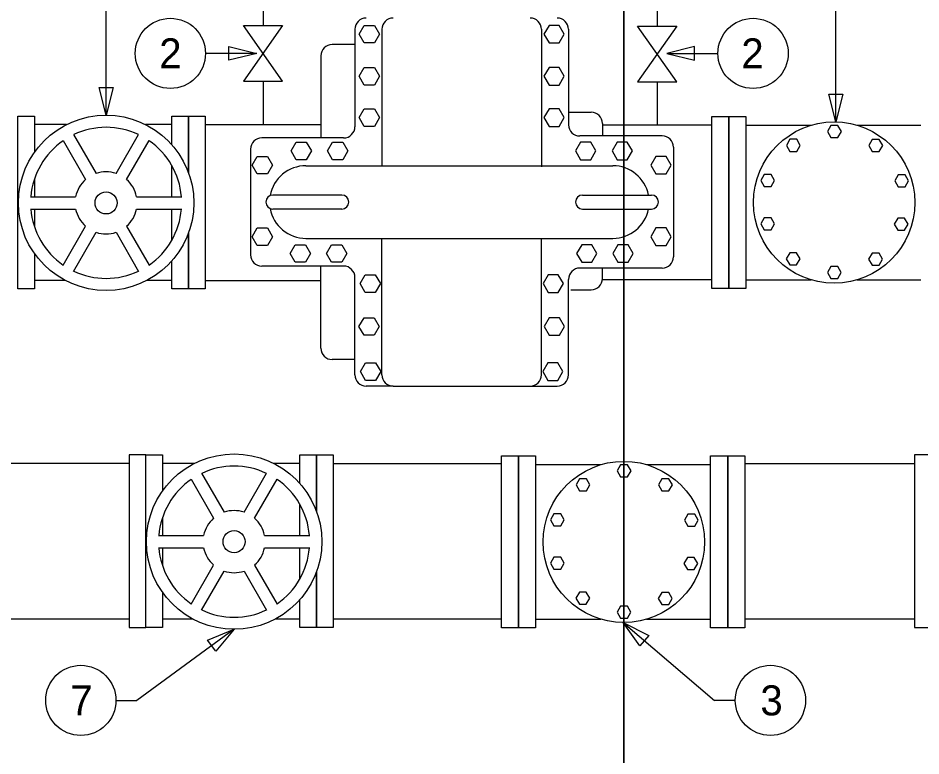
# Model space of a CAD drawing. Extents: x 10442.9 to 10533.9, y 10030 to 10079.1.
# Drawn here: x 10473.91 to 10495.58, y 10048.04 to 10065.76 of the extents above; entities that cross this region are included whole.
import ezdxf

# ---------------------------------------------------------------- set-up
doc = ezdxf.new("R2010")
doc.units = 0
for name, color, linetype in [('G-ANNO-NPLT', 7, 'Continuous'), ('G-ANNO-SYMB', 7, 'Continuous'), ('G-DETL-LINE', 7, 'Continuous')]:
    doc.layers.add(name, color=color, linetype=linetype)

msp = doc.modelspace()

# ---------------------------------------------------------------- linework, layer by layer
at = {"layer": 'G-ANNO-NPLT'}
for points in [[(10442.947, 10029.978), (10442.947, 10079.12), (10488.447, 10079.12), (10488.447, 10029.978)], [(10488.447, 10029.978), (10488.447, 10079.12), (10533.947, 10079.12), (10533.947, 10029.978)]]:
    msp.add_lwpolyline(points, close=True, dxfattribs=at)
at = {"layer": 'G-ANNO-SYMB'}
for centre in [(10477.565, 10064.909), (10491.55, 10064.909), (10475.416, 10049.374), (10491.967, 10049.374)]:
    msp.add_circle(centre, 0.843, dxfattribs=at)
at = {"layer": 'G-DETL-LINE'}
for p, q in [((10476.023, 10063.425), (10476.023, 10066.199)), ((10479.79, 10066.083), (10479.79, 10065.579)), ((10493.538, 10063.263), (10493.538, 10066.199)), ((10489.248, 10066.067), (10489.248, 10065.563)), ((10480.259, 10064.24), (10479.321, 10065.579)), ((10479.321, 10065.579), (10480.259, 10065.579)), ((10480.259, 10065.579), (10479.321, 10064.24)), ((10481.994, 10065.488), (10481.994, 10063.149)), ((10482.644, 10065.488), (10482.644, 10062.212)), ((10486.471, 10065.488), (10486.471, 10062.188)), ((10487.121, 10065.488), (10487.121, 10063.196)), ((10489.717, 10064.224), (10488.779, 10065.563)), ((10488.779, 10065.563), (10489.717, 10065.563)), ((10489.717, 10065.563), (10488.779, 10064.224)), ((10481.994, 10065.122), (10481.448, 10065.122)), ((10479.637, 10064.909), (10478.408, 10064.909)), ((10481.178, 10064.852), (10481.178, 10062.878)), ((10489.478, 10064.909), (10490.707, 10064.909)), ((10479.321, 10064.24), (10480.259, 10064.24)), ((10479.79, 10064.24), (10479.79, 10063.2)), ((10488.779, 10064.224), (10489.717, 10064.224)), ((10489.248, 10064.224), (10489.248, 10063.184)), ((10487.121, 10063.497), (10487.667, 10063.497)), ((10475.076, 10063.2), (10474.301, 10063.2)), ((10477.6, 10063.2), (10476.969, 10063.2)), ((10478.401, 10063.2), (10481.179, 10063.2)), ((10487.937, 10063.226), (10487.937, 10062.926)), ((10490.559, 10063.184), (10487.937, 10063.184)), ((10491.38, 10063.184), (10492.947, 10063.184)), ((10494.043, 10063.184), (10495.579, 10063.184)), ((10475.243, 10062.964), (10475.784, 10062.027)), ((10476.262, 10062.027), (10476.803, 10062.964)), ((10481.724, 10062.878), (10479.76, 10062.878)), ((10489.37, 10062.926), (10487.391, 10062.926)), ((10474.989, 10062.818), (10475.53, 10061.881)), ((10476.516, 10061.881), (10477.057, 10062.818)), ((10489.64, 10062.656), (10489.64, 10060.025)), ((10479.49, 10062.608), (10479.49, 10060.072)), ((10480.819, 10062.212), (10488.184, 10062.212)), ((10474.209, 10061.469), (10475.292, 10061.469)), ((10476.754, 10061.469), (10477.837, 10061.469)), ((10481.68, 10061.508), (10480.026, 10061.508)), ((10487.456, 10061.508), (10489.11, 10061.508)), ((10474.209, 10061.171), (10475.292, 10061.171)), ((10476.754, 10061.171), (10477.837, 10061.171)), ((10481.68, 10061.172), (10480.026, 10061.172)), ((10487.456, 10061.172), (10489.11, 10061.172)), ((10474.989, 10059.822), (10475.53, 10060.759)), ((10476.516, 10060.759), (10477.057, 10059.822)), ((10475.243, 10059.676), (10475.784, 10060.613)), ((10476.262, 10060.613), (10476.803, 10059.676)), ((10480.819, 10060.468), (10488.184, 10060.468)), ((10482.644, 10057.192), (10482.644, 10060.468)), ((10486.471, 10057.192), (10486.471, 10060.443)), ((10481.724, 10059.802), (10479.76, 10059.802)), ((10481.178, 10057.828), (10481.178, 10059.802)), ((10489.37, 10059.754), (10487.391, 10059.754)), ((10487.937, 10059.503), (10487.937, 10059.754)), ((10475.039, 10059.46), (10474.301, 10059.46)), ((10477.6, 10059.46), (10477.007, 10059.46)), ((10478.401, 10059.46), (10481.179, 10059.46)), ((10481.994, 10057.192), (10481.994, 10059.532)), ((10487.121, 10057.192), (10487.121, 10059.484)), ((10490.559, 10059.471), (10487.937, 10059.471)), ((10491.38, 10059.471), (10492.947, 10059.471)), ((10494.043, 10059.471), (10495.579, 10059.471)), ((10487.173, 10059.233), (10487.667, 10059.233)), ((10481.994, 10057.558), (10481.448, 10057.558)), ((10482.914, 10056.922), (10482.265, 10056.922)), ((10482.914, 10056.922), (10486.201, 10056.922)), ((10486.201, 10056.922), (10486.85, 10056.922)), ((10476.573, 10055.066), (10473.444, 10055.066)), ((10478.149, 10055.066), (10477.374, 10055.066)), ((10480.672, 10055.066), (10480.042, 10055.066)), ((10481.473, 10055.066), (10485.512, 10055.066)), ((10486.332, 10055.035), (10487.899, 10055.035)), ((10488.995, 10055.035), (10490.531, 10055.035)), ((10491.351, 10055.066), (10495.421, 10055.066)), ((10478.315, 10054.83), (10478.856, 10053.893)), ((10479.334, 10053.893), (10479.875, 10054.83)), ((10478.061, 10054.684), (10478.602, 10053.747)), ((10479.588, 10053.747), (10480.129, 10054.684)), ((10477.281, 10053.335), (10478.364, 10053.335)), ((10479.826, 10053.335), (10480.909, 10053.335)), ((10477.281, 10053.037), (10478.364, 10053.037)), ((10479.826, 10053.037), (10480.909, 10053.037)), ((10478.061, 10051.688), (10478.602, 10052.625)), ((10478.315, 10051.542), (10478.856, 10052.479)), ((10479.334, 10052.479), (10479.875, 10051.542)), ((10479.588, 10052.625), (10480.129, 10051.688)), ((10476.573, 10051.325), (10473.444, 10051.325)), ((10478.111, 10051.325), (10477.374, 10051.325)), ((10480.672, 10051.325), (10480.079, 10051.325)), ((10485.512, 10051.325), (10481.473, 10051.325)), ((10486.332, 10051.321), (10487.899, 10051.321)), ((10488.433, 10051.242), (10490.625, 10049.374)), ((10488.995, 10051.321), (10490.531, 10051.321)), ((10495.421, 10051.325), (10491.351, 10051.325)), ((10479.095, 10051.081), (10476.759, 10049.374)), ((10476.259, 10049.374), (10476.759, 10049.374)), ((10491.125, 10049.374), (10490.625, 10049.374))]:
    msp.add_line(p, q, dxfattribs=at)
for points in [[(10482.096, 10065.372), (10482.218, 10065.583), (10482.462, 10065.583), (10482.584, 10065.372), (10482.462, 10065.161), (10482.218, 10065.161)], [(10487.018, 10065.372), (10486.896, 10065.583), (10486.653, 10065.583), (10486.531, 10065.372), (10486.653, 10065.161), (10486.896, 10065.161)], [(10478.97, 10065.076), (10479.637, 10064.909), (10478.97, 10064.743)], [(10490.145, 10065.076), (10489.478, 10064.909), (10490.145, 10064.743)], [(10482.096, 10064.359), (10482.218, 10064.57), (10482.462, 10064.57), (10482.584, 10064.359), (10482.462, 10064.147), (10482.218, 10064.147)], [(10487.018, 10064.359), (10486.896, 10064.57), (10486.653, 10064.57), (10486.531, 10064.359), (10486.653, 10064.147), (10486.896, 10064.147)], [(10476.19, 10064.091), (10476.023, 10063.425), (10475.856, 10064.091)], [(10493.704, 10063.93), (10493.538, 10063.263), (10493.371, 10063.93)], [(10482.095, 10063.367), (10482.217, 10063.579), (10482.461, 10063.579), (10482.582, 10063.367), (10482.461, 10063.156), (10482.217, 10063.156)], [(10487.02, 10063.367), (10486.898, 10063.579), (10486.654, 10063.579), (10486.532, 10063.367), (10486.654, 10063.156), (10486.898, 10063.156)], [(10490.559, 10063.393), (10490.97, 10063.393), (10490.97, 10059.267), (10490.559, 10059.267)], [(10490.97, 10063.393), (10491.38, 10063.393), (10491.38, 10059.267), (10490.97, 10059.267)], [(10493.67, 10063.033), (10493.587, 10063.178), (10493.42, 10063.178), (10493.337, 10063.033), (10493.42, 10062.889), (10493.587, 10062.889)], [(10492.683, 10062.701), (10492.6, 10062.846), (10492.433, 10062.846), (10492.35, 10062.701), (10492.433, 10062.557), (10492.6, 10062.557)], [(10494.661, 10062.698), (10494.578, 10062.843), (10494.411, 10062.843), (10494.328, 10062.698), (10494.411, 10062.554), (10494.578, 10062.554)], [(10480.462, 10062.567), (10480.584, 10062.778), (10480.827, 10062.778), (10480.949, 10062.567), (10480.827, 10062.356), (10480.584, 10062.356)], [(10481.338, 10062.567), (10481.46, 10062.778), (10481.704, 10062.778), (10481.826, 10062.567), (10481.704, 10062.356), (10481.46, 10062.356)], [(10487.777, 10062.567), (10487.655, 10062.778), (10487.411, 10062.778), (10487.289, 10062.567), (10487.411, 10062.356), (10487.655, 10062.356)], [(10488.653, 10062.567), (10488.531, 10062.778), (10488.287, 10062.778), (10488.165, 10062.567), (10488.287, 10062.356), (10488.531, 10062.356)], [(10479.53, 10062.225), (10479.652, 10062.436), (10479.896, 10062.436), (10480.018, 10062.225), (10479.896, 10062.014), (10479.652, 10062.014)], [(10489.584, 10062.225), (10489.462, 10062.436), (10489.218, 10062.436), (10489.096, 10062.225), (10489.218, 10062.014), (10489.462, 10062.014)], [(10492.068, 10061.861), (10491.984, 10062.005), (10491.818, 10062.005), (10491.734, 10061.861), (10491.818, 10061.717), (10491.984, 10061.717)], [(10495.283, 10061.849), (10495.2, 10061.993), (10495.033, 10061.993), (10494.95, 10061.849), (10495.033, 10061.705), (10495.2, 10061.705)], [(10492.068, 10060.82), (10491.984, 10060.964), (10491.818, 10060.964), (10491.734, 10060.82), (10491.818, 10060.675), (10491.984, 10060.675)], [(10495.271, 10060.809), (10495.188, 10060.954), (10495.021, 10060.954), (10494.938, 10060.809), (10495.021, 10060.665), (10495.188, 10060.665)], [(10479.53, 10060.505), (10479.652, 10060.717), (10479.896, 10060.717), (10480.018, 10060.505), (10479.896, 10060.294), (10479.652, 10060.294)], [(10489.584, 10060.505), (10489.462, 10060.717), (10489.218, 10060.717), (10489.096, 10060.505), (10489.218, 10060.294), (10489.462, 10060.294)], [(10480.442, 10060.104), (10480.564, 10060.315), (10480.808, 10060.315), (10480.93, 10060.104), (10480.808, 10059.893), (10480.564, 10059.893)], [(10481.311, 10060.104), (10481.433, 10060.315), (10481.677, 10060.315), (10481.799, 10060.104), (10481.677, 10059.893), (10481.433, 10059.893)], [(10487.804, 10060.104), (10487.682, 10060.315), (10487.438, 10060.315), (10487.316, 10060.104), (10487.438, 10059.893), (10487.682, 10059.893)], [(10488.673, 10060.104), (10488.551, 10060.315), (10488.307, 10060.315), (10488.185, 10060.104), (10488.307, 10059.893), (10488.551, 10059.893)], [(10492.679, 10059.977), (10492.596, 10060.121), (10492.43, 10060.121), (10492.346, 10059.977), (10492.43, 10059.833), (10492.596, 10059.833)], [(10494.657, 10059.968), (10494.574, 10060.112), (10494.408, 10060.112), (10494.324, 10059.968), (10494.408, 10059.824), (10494.574, 10059.824)], [(10482.118, 10059.383), (10482.24, 10059.594), (10482.484, 10059.594), (10482.606, 10059.383), (10482.484, 10059.172), (10482.24, 10059.172)], [(10486.997, 10059.383), (10486.875, 10059.594), (10486.631, 10059.594), (10486.509, 10059.383), (10486.631, 10059.172), (10486.875, 10059.172)], [(10493.667, 10059.646), (10493.584, 10059.79), (10493.417, 10059.79), (10493.334, 10059.646), (10493.417, 10059.502), (10493.584, 10059.502)], [(10482.092, 10058.352), (10482.214, 10058.563), (10482.458, 10058.563), (10482.58, 10058.352), (10482.458, 10058.141), (10482.214, 10058.141)], [(10487.022, 10058.352), (10486.901, 10058.563), (10486.657, 10058.563), (10486.535, 10058.352), (10486.657, 10058.141), (10486.901, 10058.141)], [(10482.126, 10057.271), (10482.248, 10057.482), (10482.492, 10057.482), (10482.614, 10057.271), (10482.492, 10057.059), (10482.248, 10057.059)], [(10486.988, 10057.271), (10486.866, 10057.482), (10486.623, 10057.482), (10486.501, 10057.271), (10486.623, 10057.059), (10486.866, 10057.059)], [(10485.512, 10055.243), (10485.922, 10055.243), (10485.922, 10051.117), (10485.512, 10051.117)], [(10485.922, 10055.243), (10486.332, 10055.243), (10486.332, 10051.117), (10485.922, 10051.117)], [(10490.531, 10055.244), (10490.941, 10055.244), (10490.941, 10051.118), (10490.531, 10051.118)], [(10490.941, 10055.244), (10491.351, 10055.244), (10491.351, 10051.118), (10490.941, 10051.118)], [(10488.622, 10054.884), (10488.539, 10055.028), (10488.372, 10055.028), (10488.289, 10054.884), (10488.372, 10054.739), (10488.539, 10054.739)], [(10487.635, 10054.552), (10487.552, 10054.696), (10487.385, 10054.696), (10487.302, 10054.552), (10487.385, 10054.407), (10487.552, 10054.407)], [(10489.614, 10054.548), (10489.53, 10054.693), (10489.364, 10054.693), (10489.28, 10054.548), (10489.364, 10054.404), (10489.53, 10054.404)], [(10487.02, 10053.711), (10486.937, 10053.856), (10486.77, 10053.856), (10486.687, 10053.711), (10486.77, 10053.567), (10486.937, 10053.567)], [(10490.235, 10053.699), (10490.152, 10053.843), (10489.985, 10053.843), (10489.902, 10053.699), (10489.985, 10053.555), (10490.152, 10053.555)], [(10487.02, 10052.67), (10486.937, 10052.814), (10486.77, 10052.814), (10486.687, 10052.67), (10486.77, 10052.526), (10486.937, 10052.526)], [(10490.223, 10052.66), (10490.14, 10052.804), (10489.973, 10052.804), (10489.89, 10052.66), (10489.973, 10052.515), (10490.14, 10052.515)], [(10487.632, 10051.827), (10487.548, 10051.971), (10487.382, 10051.971), (10487.298, 10051.827), (10487.382, 10051.683), (10487.548, 10051.683)], [(10489.61, 10051.818), (10489.526, 10051.962), (10489.36, 10051.962), (10489.276, 10051.818), (10489.36, 10051.674), (10489.526, 10051.674)], [(10488.619, 10051.496), (10488.536, 10051.64), (10488.369, 10051.64), (10488.286, 10051.496), (10488.369, 10051.352), (10488.536, 10051.352)], [(10488.832, 10050.683), (10488.433, 10051.242), (10489.048, 10050.936)], [(10478.459, 10050.823), (10479.095, 10051.081), (10478.655, 10050.553)]]:
    msp.add_lwpolyline(points, close=True, dxfattribs=at)
for points in [[(10474.301, 10060.109), (10474.301, 10059.257), (10473.901, 10059.257), (10473.901, 10063.402), (10474.301, 10063.402), (10474.301, 10062.531)], [(10477.6, 10062.714), (10477.6, 10063.402), (10478, 10063.402), (10478, 10062.041)], [(10478, 10062.041), (10478, 10063.402), (10478.401, 10063.402), (10478.401, 10059.257), (10478, 10059.257), (10478, 10060.599)], [(10477.6, 10061.469), (10477.6, 10062.217)], [(10474.301, 10061.892), (10474.301, 10061.469)], [(10474.301, 10061.171), (10474.301, 10060.748)], [(10477.6, 10060.423), (10477.6, 10061.171)], [(10478, 10060.599), (10478, 10059.257), (10477.6, 10059.257), (10477.6, 10059.926)], [(10476.973, 10053.907), (10476.973, 10055.268), (10476.573, 10055.268), (10476.573, 10051.123), (10476.973, 10051.123), (10476.973, 10052.465)], [(10477.374, 10051.975), (10477.374, 10051.123), (10476.973, 10051.123), (10476.973, 10055.268), (10477.374, 10055.268), (10477.374, 10054.397)], [(10480.672, 10054.58), (10480.672, 10055.268), (10481.073, 10055.268), (10481.073, 10053.907)], [(10481.073, 10053.907), (10481.073, 10055.268), (10481.473, 10055.268), (10481.473, 10051.123), (10481.073, 10051.123), (10481.073, 10052.465)], [(10495.822, 10053.907), (10495.822, 10055.268), (10495.421, 10055.268), (10495.421, 10051.123), (10495.822, 10051.123), (10495.822, 10052.465)], [(10480.672, 10053.335), (10480.672, 10054.083)], [(10477.374, 10053.758), (10477.374, 10053.335)], [(10477.374, 10053.037), (10477.374, 10052.614)], [(10480.672, 10052.289), (10480.672, 10053.037)], [(10481.073, 10052.465), (10481.073, 10051.123), (10480.672, 10051.123), (10480.672, 10051.792)]]:
    msp.add_lwpolyline(points, dxfattribs=at)
for centre, radius in [((10476.023, 10061.32), 2.105), ((10493.495, 10061.328), 1.936), ((10476.023, 10061.32), 0.265), ((10479.095, 10053.186), 2.105), ((10488.447, 10053.178), 1.936), ((10479.095, 10053.186), 0.265)]:
    msp.add_circle(centre, radius, dxfattribs=at)
for centre, radius, start, end in [((10482.265, 10065.488), 0.27, 90, 180), ((10482.914, 10065.488), 0.27, 90, 180), ((10486.201, 10065.488), 0.27, 0, 90), ((10486.85, 10065.488), 0.27, 0, 90), ((10481.448, 10064.852), 0.27, 90, 180), ((10487.667, 10063.226), 0.27, 0, 90), ((10476.023, 10061.32), 1.814, 64.6295, 115.3705), ((10481.724, 10063.149), 0.27, 270, 0), ((10487.391, 10063.196), 0.27, 180, 270), ((10479.76, 10062.608), 0.27, 90, 180), ((10489.37, 10062.656), 0.27, 0, 90), ((10476.023, 10061.32), 1.814, 124.6295, 175.2858), ((10476.023, 10061.32), 1.814, 4.7142, 55.3705), ((10480.819, 10061.34), 0.872, 90, 169.7691), ((10488.184, 10061.34), 0.872, 11.1065, 90), ((10476.023, 10061.32), 0.746, 71.3127, 108.6873), ((10476.023, 10061.32), 0.746, 131.3127, 168.4779), ((10476.023, 10061.32), 0.746, 11.5221, 48.6873), ((10480.026, 10061.34), 0.168, 90, 270), ((10481.68, 10061.34), 0.168, 270, 90), ((10487.456, 10061.34), 0.168, 90, 270), ((10489.11, 10061.34), 0.168, 270, 90), ((10476.023, 10061.32), 1.814, 184.7142, 235.3705), ((10476.023, 10061.32), 0.746, 191.5221, 228.6873), ((10476.023, 10061.32), 0.746, 311.3127, 348.4779), ((10476.023, 10061.32), 1.814, 304.6295, 355.2858), ((10480.819, 10061.34), 0.872, 190.2309, 270), ((10488.184, 10061.34), 0.872, 270, 348.8935), ((10476.023, 10061.32), 0.746, 251.3127, 288.6873), ((10479.76, 10060.072), 0.27, 180, 270), ((10489.37, 10060.025), 0.27, 270, 0), ((10481.724, 10059.532), 0.27, 0, 90), ((10476.023, 10061.32), 1.814, 244.6295, 295.3705), ((10487.391, 10059.484), 0.27, 90, 180), ((10487.667, 10059.503), 0.27, 270, 0), ((10481.448, 10057.828), 0.27, 180, 270), ((10482.265, 10057.192), 0.27, 180, 270), ((10482.914, 10057.192), 0.27, 180, 270), ((10486.201, 10057.192), 0.27, 270, 0), ((10486.85, 10057.192), 0.27, 270, 0), ((10479.095, 10053.186), 1.814, 64.6295, 115.3705), ((10479.095, 10053.186), 1.814, 124.6295, 175.2858), ((10479.095, 10053.186), 1.814, 4.7142, 55.3705), ((10479.095, 10053.186), 0.746, 131.3127, 168.4779), ((10479.095, 10053.186), 0.746, 71.3127, 108.6873), ((10479.095, 10053.186), 0.746, 11.5221, 48.6873), ((10479.095, 10053.186), 1.814, 184.7142, 235.3705), ((10479.095, 10053.186), 0.746, 191.5221, 228.6873), ((10479.095, 10053.186), 0.746, 311.3127, 348.4779), ((10479.095, 10053.186), 1.814, 304.6295, 355.2858), ((10479.095, 10053.186), 0.746, 251.3127, 288.6873), ((10479.095, 10053.186), 1.814, 244.6295, 295.3705)]:
    msp.add_arc(centre, radius, start, end, dxfattribs=at)

# ---------------------------------------------------------------- texts
at = {"layer": 'G-ANNO-SYMB'}
for s, p in [('2', (10477.297, 10064.549)), ('2', (10491.268, 10064.549)), ('7', (10475.164, 10049.014)), ('3', (10491.725, 10049.014))]:
    msp.add_text(s, height=0.721, dxfattribs=at).set_placement(p)

doc.saveas('drawing.dxf')
